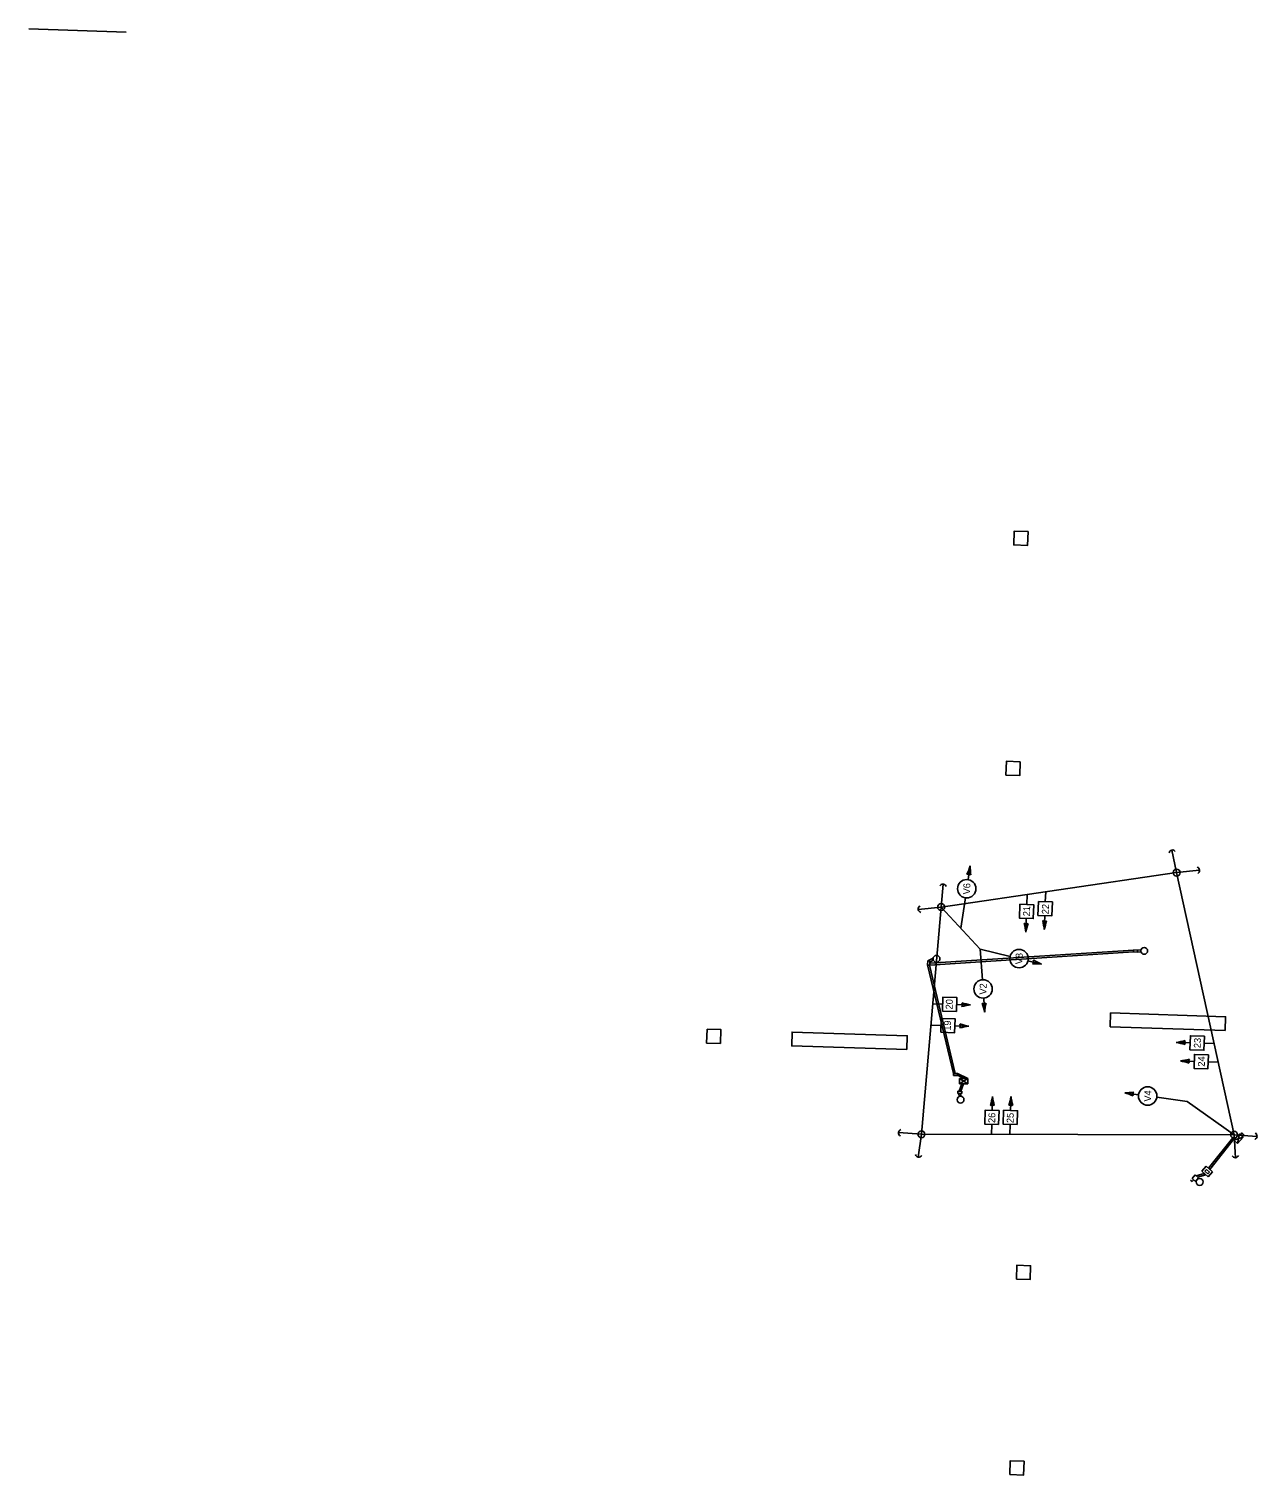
# Model space of a CAD drawing. Extents: x 981632 to 1292532, y 220574 to 1843876.
# Drawn here: x 992067 to 992601, y 1843188 to 1843816 of the extents above; entities that cross this region are included whole.
import ezdxf

# ---------------------------------------------------------------- set-up
doc = ezdxf.new("R2010")
doc.units = 0
for name, color, linetype in [('No Plot', 7, 'Continuous'), ('R_Existing Signal', 7, 'Continuous'), ('T_Drafting', 7, 'Continuous'), ('T_Indications', 7, 'Continuous'), ('V-SIGNAL-CONDUIT', 7, 'Continuous'), ('V-SIGNAL-CONTROLLER', 7, 'Continuous'), ('V-SIGNAL-HEAD-MOT', 7, 'Continuous'), ('V-SIGNAL-LOOP-MOT', 7, 'Continuous'), ('V-SIGNAL-POLE', 7, 'Continuous'), ('V-SIGNAL-POLE-MOT', 7, 'Continuous')]:
    doc.layers.add(name, color=color, linetype=linetype)

msp = doc.modelspace()

# ---------------------------------------------------------------- linework, layer by layer
at = {"layer": 'No Plot'}
msp.add_line((992109.34, 1843814.21), (992067.09, 1843815.66), dxfattribs=at)
at = {"layer": 'R_Existing Signal'}
for p, q in [((992457.54, 1843410.97), (992459.9, 1843412.24)), ((992458.41, 1843409.19), (992546.91, 1843414.88)), ((992458.43, 1843410.07), (992546.96, 1843415.63)), ((992546.98, 1843415.83), (992546.92, 1843414.91)), ((992546.92, 1843414.91), (992548.66, 1843414.79)), ((992548.72, 1843415.71), (992546.98, 1843415.83)), ((992548.66, 1843414.79), (992548.72, 1843415.71)), ((992548.66, 1843414.79), (992550.16, 1843414.89)), ((992548.72, 1843415.71), (992550.15, 1843415.8)), ((992457.54, 1843410.97), (992457.49, 1843409.22)), ((992457.49, 1843409.22), (992458.41, 1843409.19)), ((992457.49, 1843409.22), (992468.67, 1843362.15)), ((992458.46, 1843410.94), (992457.54, 1843410.97)), ((992458.25, 1843409.2), (992469.43, 1843362.16)), ((992458.41, 1843409.19), (992458.46, 1843410.94)), ((992458.44, 1843410.43), (992459.98, 1843411.3)), ((992470.42, 1843362.16), (992468.67, 1843362.15)), ((992468.67, 1843362.15), (992468.67, 1843361.24)), ((992470.42, 1843361.24), (992470.42, 1843362.16)), ((992475, 1843359.93), (992470.42, 1843362.16)), ((992468.67, 1843361.24), (992470.42, 1843361.24)), ((992473.31, 1843359.93), (992470.42, 1843361.33)), ((992471.16, 1843354.42), (992472.36, 1843357.68)), ((992471.34, 1843359.93), (992475, 1843359.93)), ((992471.34, 1843357.68), (992475, 1843359.93)), ((992471.34, 1843359.93), (992475, 1843357.68)), ((992471.34, 1843357.68), (992471.34, 1843359.93)), ((992471.34, 1843357.68), (992475, 1843357.68)), ((992471.95, 1843354.42), (992473.15, 1843357.68)), ((992475, 1843357.68), (992475, 1843359.93)), ((992472.31, 1843354.38), (992470.56, 1843354.38)), ((992470.56, 1843354.38), (992470.57, 1843353.46)), ((992470.57, 1843353.46), (992472.32, 1843353.47)), ((992471.24, 1843352.13), (992471.06, 1843353.47)), ((992471.98, 1843352.23), (992471.81, 1843353.47)), ((992472.32, 1843353.47), (992472.31, 1843354.38))]:
    msp.add_line(p, q, dxfattribs=at)
for centre in [(992461.36, 1843411.89), (992551.58, 1843415.35), (992471.8, 1843350.74)]:
    msp.add_circle(centre, 1.5, dxfattribs=at)
at = {"layer": 'T_Drafting'}
for p, q in [((992573.69, 1843318.06), (992572.38, 1843316.55)), ((992573.69, 1843318.06), (992575.2, 1843316.75)), ((992571.72, 1843315.8), (992572.48, 1843315.14)), ((992572.38, 1843316.55), (992573.89, 1843315.24)), ((992573.13, 1843315.9), (992572.48, 1843315.14)), ((992575.2, 1843316.75), (992573.89, 1843315.24))]:
    msp.add_line(p, q, dxfattribs=at)
msp.add_circle((992575.68, 1843315.01), 1.5, dxfattribs=at)
at = {"layer": 'T_Indications'}
for p, q in [((992475.1, 1843446.29), (992476.01, 1843452.28)), ((992500.75, 1843439.85), (992500.59, 1843435.51)), ((992508.8, 1843441.03), (992508.63, 1843436.69)), ((992500.38, 1843429.45), (992500.15, 1843423.41)), ((992508.43, 1843430.63), (992508.2, 1843424.59)), ((992501.1, 1843411.06), (992506.99, 1843409.63)), ((992481.86, 1843394.82), (992482.28, 1843388.77)), ((992459.74, 1843392.39), (992464.08, 1843392.25)), ((992470.14, 1843392.07), (992476.18, 1843391.87)), ((992458.94, 1843383.15), (992463.28, 1843383.01)), ((992469.34, 1843382.83), (992475.38, 1843382.63)), ((992571.55, 1843375.44), (992565.52, 1843375.63)), ((992581.96, 1843375.13), (992577.62, 1843375.27)), ((992573.32, 1843367.36), (992567.29, 1843367.56)), ((992583.73, 1843367.06), (992579.39, 1843367.2)), ((992485.53, 1843346.08), (992485.74, 1843352.11)), ((992493.51, 1843346.07), (992493.73, 1843352.11)), ((992549.12, 1843352.89), (992543.12, 1843353.73)), ((992485.18, 1843335.67), (992485.34, 1843340.02)), ((992493.17, 1843335.66), (992493.32, 1843340.01))]:
    msp.add_line(p, q, dxfattribs=at)
for points in [[(992497.57, 1843435.62), (992503.63, 1843435.39), (992503.4, 1843429.34), (992497.34, 1843429.57)], [(992505.62, 1843436.8), (992511.68, 1843436.57), (992511.45, 1843430.51), (992505.39, 1843430.74)], [(992463.98, 1843389.23), (992464.18, 1843395.29), (992470.24, 1843395.09), (992470.04, 1843389.03)], [(992463.18, 1843379.99), (992463.38, 1843386.05), (992469.44, 1843385.85), (992469.24, 1843379.79)], [(992577.71, 1843378.28), (992577.52, 1843372.22), (992571.46, 1843372.41), (992571.65, 1843378.48)], [(992579.48, 1843370.21), (992579.29, 1843364.15), (992573.23, 1843364.34), (992573.42, 1843370.4)], [(992488.35, 1843339.91), (992482.29, 1843340.13), (992482.5, 1843346.19), (992488.56, 1843345.97)], [(992496.34, 1843339.9), (992490.28, 1843340.12), (992490.49, 1843346.18), (992496.55, 1843345.96)]]:
    msp.add_lwpolyline(points, close=True, dxfattribs=at)
for centre in [(992474.49, 1843442.33), (992497.21, 1843412), (992481.59, 1843398.81), (992553.09, 1843352.34)]:
    msp.add_circle(centre, 4, dxfattribs=at)
for centre, radius, start, end in [((992447.87, 1843461.03), 29.47, 334.98678, 342.72489), ((992505.48, 1843452.25), 29.47, 179.94152, 187.67964), ((992475.22, 1843447.08), 1.63, 49.48589, 113.18053), ((992500.35, 1843428.68), 1.63, 235.9812, 299.67583), ((992470.86, 1843420.11), 29.47, 6.43683, 14.17494), ((992529.1, 1843417.9), 29.47, 161.48208, 169.2202), ((992508.4, 1843429.85), 1.63, 235.9812, 299.67583), ((992478.91, 1843421.29), 29.47, 6.43683, 14.17494), ((992537.15, 1843419.08), 29.47, 161.48208, 169.2202), ((992501.87, 1843410.87), 1.63, 314.54653, 18.24117), ((992504.43, 1843380.27), 29.47, 85.00216, 92.74028), ((992518.14, 1843436.92), 29.47, 240.04742, 247.78553), ((992470.92, 1843392.04), 1.63, 326.23979, 29.93442), ((992479.62, 1843362.59), 29.47, 96.69542, 104.43353), ((992481.56, 1843420.84), 29.47, 251.74067, 259.47879), ((992481.92, 1843394.02), 1.63, 242.10991, 305.80455), ((992453.52, 1843382.36), 29.47, 12.56554, 20.30366), ((992511.66, 1843386.38), 29.47, 167.6108, 175.34891), ((992470.12, 1843382.8), 1.63, 326.23979, 29.93442), ((992478.82, 1843353.35), 29.47, 96.69542, 104.43353), ((992480.76, 1843411.6), 29.47, 251.74067, 259.47879), ((992562.03, 1843404.89), 29.47, 276.79299, 284.5311), ((992560.18, 1843346.64), 29.47, 71.83824, 79.57635), ((992570.78, 1843375.46), 1.63, 146.33735, 210.03199), ((992563.8, 1843396.82), 29.47, 276.79299, 284.5311), ((992572.55, 1843367.39), 1.63, 146.33735, 210.03199), ((992561.96, 1843338.57), 29.47, 71.83824, 79.57635), ((992456.78, 1843357.56), 29.47, 341.62475, 349.36287), ((992515.02, 1843355.49), 29.47, 186.5795, 194.31762), ((992464.76, 1843357.55), 29.47, 341.62475, 349.36287), ((992523, 1843355.48), 29.47, 186.5795, 194.31762), ((992542.76, 1843383.2), 29.47, 270.69001, 278.42812), ((992534.73, 1843325.47), 29.47, 65.73526, 73.47337), ((992548.33, 1843353), 1.63, 140.23437, 203.92901), ((992485.55, 1843346.85), 1.63, 56.12387, 119.8185), ((992493.54, 1843346.84), 1.63, 56.12387, 119.8185)]:
    msp.add_arc(centre, radius, start, end, dxfattribs=at)
at = {"layer": 'V-SIGNAL-CONDUIT'}
for p, q in [((992579.48, 1843320.97), (992590.02, 1843334.17)), ((992580.04, 1843320.48), (992590.87, 1843334.05)), ((992576.57, 1843319.64), (992578.49, 1843321.84)), ((992579.39, 1843317.17), (992576.57, 1843319.64)), ((992577.98, 1843319.74), (992578.58, 1843320.43)), ((992579.29, 1843318.59), (992577.98, 1843319.74)), ((992578.49, 1843321.84), (992581.31, 1843319.37)), ((992578.58, 1843320.43), (992579.9, 1843319.28)), ((992579.9, 1843319.28), (992579.29, 1843318.59)), ((992581.31, 1843319.37), (992579.39, 1843317.17))]:
    msp.add_line(p, q, dxfattribs=at)
at = {"layer": 'V-SIGNAL-CONTROLLER'}
for p, q in [((992590.54, 1843333.14), (992592.96, 1843335.9)), ((992590.54, 1843333.14), (992594.52, 1843334.53)), ((992590.54, 1843333.14), (992592.11, 1843331.77)), ((992592.11, 1843331.77), (992592.96, 1843335.9)), ((992592.11, 1843331.77), (992594.52, 1843334.53)), ((992592.96, 1843335.9), (992594.52, 1843334.53)), ((992577.64, 1843318.7), (992574.1, 1843317.7)), ((992578.31, 1843318.11), (992574.78, 1843317.11))]:
    msp.add_line(p, q, dxfattribs=at)
msp.add_lwpolyline([(992593.36, 1843335.54), (992594.02, 1843336.3), (992594.77, 1843335.64), (992594.11, 1843334.89)], close=True, dxfattribs=at)
at = {"layer": 'V-SIGNAL-LOOP-MOT'}
for points in [[(992501.15, 1843597.38), (992495.15, 1843597.59), (992494.95, 1843591.59), (992500.94, 1843591.39)], [(992497.72, 1843497.44), (992491.73, 1843497.65), (992491.52, 1843491.65), (992497.52, 1843491.45)], [(992586.78, 1843380.79), (992586.97, 1843386.78), (992537, 1843388.38), (992536.8, 1843382.39)], [(992361.68, 1843381.34), (992361.48, 1843375.34), (992367.48, 1843375.14), (992367.67, 1843381.14)], [(992448.43, 1843372.48), (992448.63, 1843378.48), (992398.65, 1843380.08), (992398.46, 1843374.08)], [(992496.05, 1843272.84), (992502.04, 1843272.64), (992502.25, 1843278.64), (992496.25, 1843278.84)], [(992493.17, 1843187.94), (992499.16, 1843187.74), (992499.37, 1843193.74), (992493.37, 1843193.94)]]:
    msp.add_lwpolyline(points, close=True, dxfattribs=at)
at = {"layer": 'V-SIGNAL-POLE'}
for p, q in [((992473.89, 1843438.38), (992471.89, 1843425.23)), ((992493.32, 1843412.94), (992480.39, 1843416.07)), ((992481.31, 1843402.8), (992480.39, 1843416.07)), ((992557.05, 1843351.79), (992570.22, 1843349.96))]:
    msp.add_line(p, q, dxfattribs=at)
msp.add_circle((992565.68, 1843449.35), 1.5, dxfattribs=at)
at = {"layer": 'V-SIGNAL-POLE-MOT'}
for p, q in [((992563.54, 1843459.12), (992565.68, 1843449.35)), ((992575.63, 1843450.38), (992565.68, 1843449.35)), ((992463.38, 1843434.38), (992565.68, 1843449.35)), ((992464.24, 1843444.35), (992463.38, 1843434.38)), ((992565.68, 1843449.35), (992590.65, 1843335.54)), ((992453.43, 1843433.35), (992463.38, 1843434.38)), ((992454.83, 1843335.71), (992463.38, 1843434.38)), ((992480.39, 1843416.07), (992463.38, 1843434.38)), ((992590.65, 1843335.54), (992570.22, 1843349.96)), ((992444.85, 1843336.43), (992454.83, 1843335.71)), ((992453.45, 1843325.81), (992454.83, 1843335.71)), ((992590.65, 1843335.54), (992454.83, 1843335.71)), ((992600.62, 1843334.82), (992590.65, 1843335.54)), ((992591.22, 1843325.55), (992590.65, 1843335.54))]:
    msp.add_line(p, q, dxfattribs=at)
for centre in [(992463.38, 1843434.38), (992454.83, 1843335.71), (992590.65, 1843335.54)]:
    msp.add_circle(centre, 1.5, dxfattribs=at)
for centre, start, end in [((992563.86, 1843457.66), 34.87201, 169.87201), ((992574.13, 1843450.23), 298.40614, 73.40614), ((992464.11, 1843442.85), 17.54822, 152.54822), ((992454.92, 1843433.51), 118.40614, 253.40614), ((992446.35, 1843336.33), 108.37023, 243.37023), ((992599.12, 1843334.92), 288.37023, 63.37023), ((992453.66, 1843327.29), 194.602, 329.602), ((992591.13, 1843327.05), 205.78453, 340.78453)]:
    msp.add_arc(centre, 1.5, start, end, dxfattribs=at)

# ---------------------------------------------------------------- texts
at = {"layer": 'V-SIGNAL-HEAD-MOT'}
for s, rotation, p in [('V6', 88.03611, (992475.91, 1843439.81)), ('21', 88.18457, (992501.93, 1843430.33)), ('22', 88.18457, (992510.09, 1843431.2)), ('V8', 88.03611, (992498.63, 1843409.48)), ('V2', 88.03611, (992483, 1843396.31)), ('20', 88.26661, (992468.33, 1843389.89)), ('19', 88.26661, (992467.54, 1843380.64)), ('23', 88.30022, (992576.13, 1843373.08)), ('24', 88.30022, (992577.9, 1843365.02)), ('V4', 88.03611, (992554.5, 1843349.83)), ('26', 88.54492, (992486.83, 1843340.57)), ('25', 88.54492, (992494.84, 1843340.53))]:
    msp.add_text(s, height=3, rotation=rotation, dxfattribs=at).set_placement(p)

doc.saveas('drawing.dxf')
